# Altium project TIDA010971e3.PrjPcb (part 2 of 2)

## Sheet TIDA010971_AutoLabeling.SchDoc
size 431 x 279 mm; Date: Not shown in title block; ApprovedBy: Not shown in title block; CheckedBy: Not shown in title block; Author: Not shown in title block; CompanyName: Not shown in title block; Engineer: Not shown in title block; Organization: Not shown in title block; Address1: Not shown in title block; Address2: Not shown in title block; Address3: Not shown in title block; Address4: Not shown in title block; DocumentNumber: 2; Revision: Use project parameter SCH_Rev; SheetNumber: 6; SheetTotal: 6; PageSetup: Record=PageOptions¦CenterHorizontal=True¦CenterVertical=True¦PrintScale=1.00¦XCorrection=1.00¦YCorrection=1.00¦PrintKind=0¦BorderSize=5000000¦LeftOffset=0¦BottomOffset=0¦Orientation=2¦PaperLength=1000¦PaperWidth=1000¦Scale=100¦PaperSource=15¦PrintQuality=600¦MediaType=1¦DitherType=10¦PaperKind=Letter¦PrintScaleMode=1
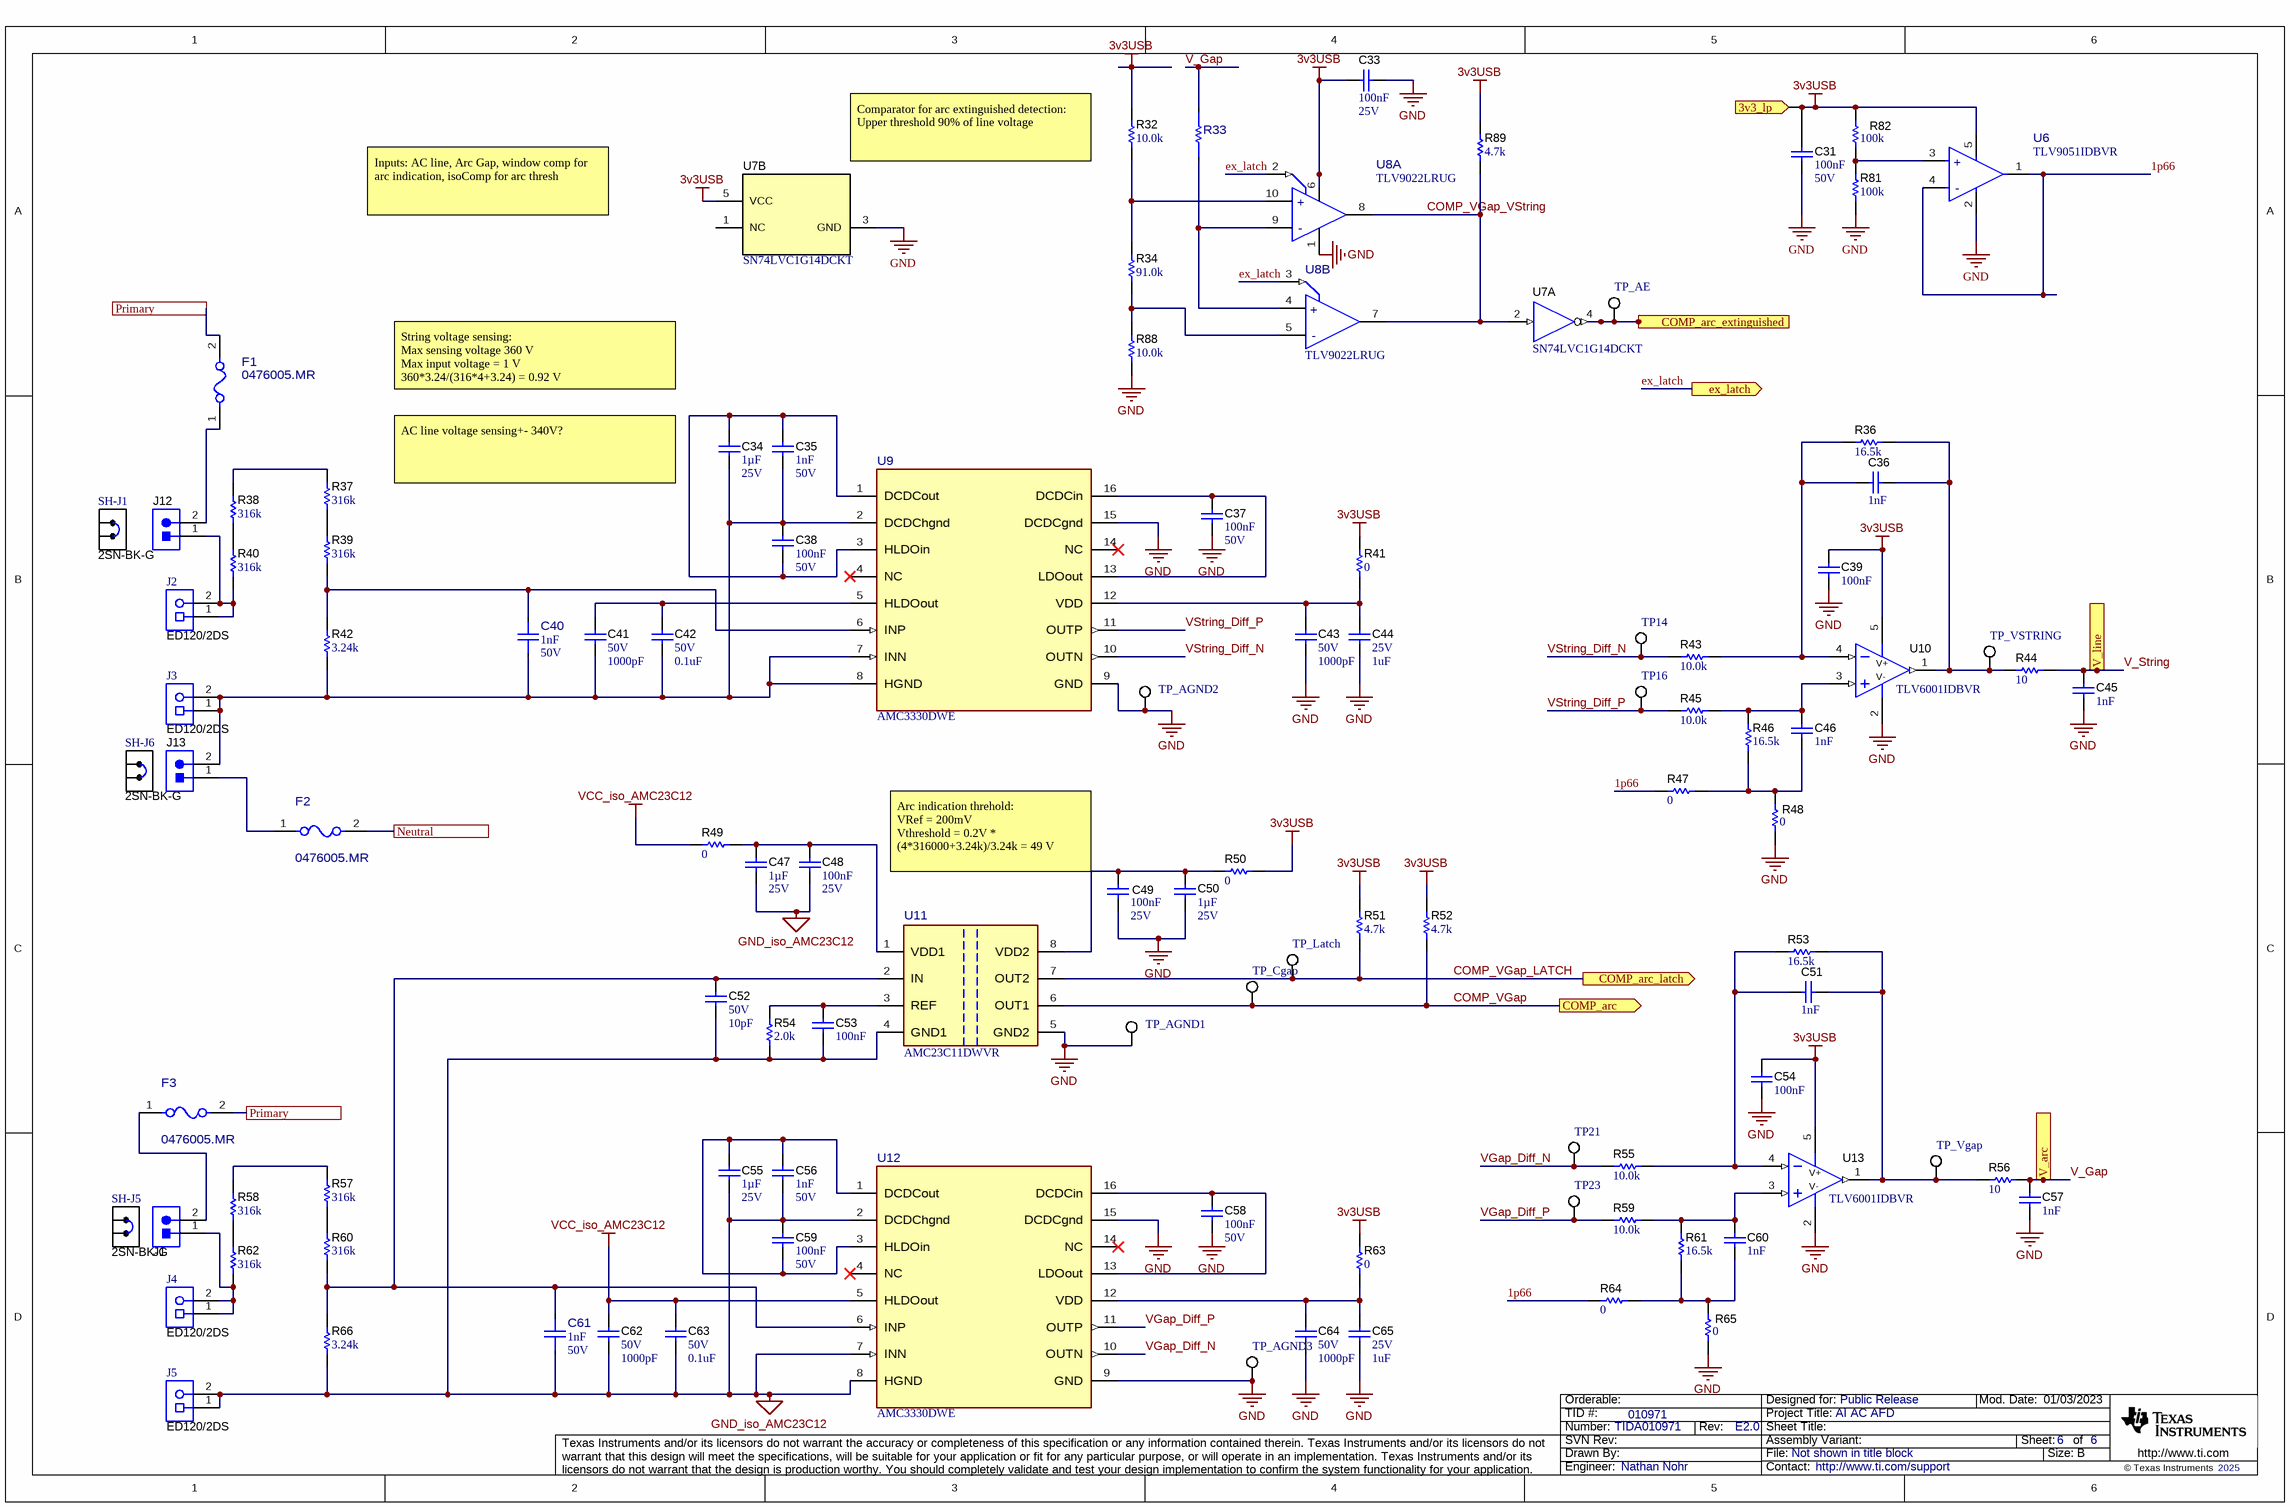
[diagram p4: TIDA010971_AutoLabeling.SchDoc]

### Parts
C31  Cap_F: 100nF  VDC_V: 50V  [0603S]  (hidden comment: C0603C104K5RACAUTO)
C33  Cap_F: 100nF  VDC_V: 25V  [0603S]  (hidden comment: C0603C104J3RACTU)
C34  Cap_F: 1µF  VDC_V: 25V  [0603S]  (hidden comment: 06033C105KAT2A)
C35  Cap_F: 1nF  VDC_V: 50V  [0603S]  (hidden comment: C0603C102K5RACTU)
C36  Cap_F: 1nF  [0603S]  (hidden comment: CL10C102JB8NNNC)
C37  Cap_F: 100nF  VDC_V: 50V  [0603S]  (hidden comment: C0603C104K5RACAUTO)
C38  Cap_F: 100nF  VDC_V: 50V  [0603S]  (hidden comment: C0603C104K5RACAUTO)
C39  Cap_F: 100nF  [0603S]  (hidden comment: C0603C104J3RAC)
C40  Cap_F: 1nF  VDC_V: 50V  [FP-C0603X102K5RAC7867_0603-MFG]  (hidden comment: C0603X102K5RAC7867)
C41  VDC_V: 50V  ValueDisplayed: 1000pF  [1206]  (hidden comment: 12065C102KAT2A)
C42  VDC_V: 50V  ValueDisplayed: 0.1uF  [1206]  (hidden comment: C1206C104K5RACTU)
C43  VDC_V: 50V  ValueDisplayed: 1000pF  [1206]  (hidden comment: 12065C102KAT2A)
C44  VDC_V: 25V  ValueDisplayed: 1uF  [1206]  (hidden comment: 12063C105KAT2A)
C45  Cap_F: 1nF  [0603S]  (hidden comment: CL10C102JB8NNNC)
C46  Cap_F: 1nF  [0603S]  (hidden comment: CL10C102JB8NNNC)
C47  Cap_F: 1µF  VDC_V: 25V  [0603S]  (hidden comment: 06033C105KAT2A)
C48  Cap_F: 100nF  VDC_V: 25V  [0603S]  (hidden comment: 06033C104KAT2A)
C49  Cap_F: 100nF  VDC_V: 25V  [0603S]  (hidden comment: 06033C104KAT2A)
C50  Cap_F: 1µF  VDC_V: 25V  [0603S]  (hidden comment: 06033C105KAT2A)
C51  Cap_F: 1nF  [0603S]  (hidden comment: CL10C102JB8NNNC)
C52  VDC_V: 50V  ValueDisplayed: 10pF  [0603S]  (hidden comment: C0603C100J5GACTU)
C53  Cap_F: 100nF  [0603S]  (hidden comment: 06033C104KAT2A)
C54  Cap_F: 100nF  [0603S]  (hidden comment: C0603C104J3RAC)
C55  Cap_F: 1µF  VDC_V: 25V  [0603S]  (hidden comment: 06033C105KAT2A)
C56  Cap_F: 1nF  VDC_V: 50V  [0603S]  (hidden comment: C0603C102K5RACTU)
C57  Cap_F: 1nF  [0603S]  (hidden comment: CL10C102JB8NNNC)
C58  Cap_F: 100nF  VDC_V: 50V  [0603S]  (hidden comment: C0603C104K5RACAUTO)
C59  Cap_F: 100nF  VDC_V: 50V  [0603S]  (hidden comment: C0603C104K5RACAUTO)
C60  Cap_F: 1nF  [0603S]  (hidden comment: CL10C102JB8NNNC)
C61  Cap_F: 1nF  VDC_V: 50V  [FP-C0603X102K5RAC7867_0603-MFG]  (hidden comment: C0603X102K5RAC7867)
C62  VDC_V: 50V  ValueDisplayed: 1000pF  [1206]  (hidden comment: 12065C102KAT2A)
C63  VDC_V: 50V  ValueDisplayed: 0.1uF  [1206]  (hidden comment: C1206C104K5RACTU)
C64  VDC_V: 50V  ValueDisplayed: 1000pF  [1206]  (hidden comment: 12065C102KAT2A)
C65  VDC_V: 25V  ValueDisplayed: 1uF  [1206]  (hidden comment: 12063C105KAT2A)
F1  0476005.MR  [FP-0476005.MR_SMT_FUSE_6MM1_2MM69-MFG]
F2  0476005.MR  [FP-0476005.MR_SMT_FUSE_6MM1_2MM69-MFG]
F3  0476005.MR  [FP-0476005.MR_SMT_FUSE_6MM1_2MM69-MFG]
J1  TSW-102-07-G-S  [TSW-102-07-G-S]  (value not drawn)
J2  ED120/2DS  [On-Shore_ED120_2DS]
J3  ED120/2DS  [On-Shore_ED120_2DS]
J4  ED120/2DS  [On-Shore_ED120_2DS]
J5  ED120/2DS  [On-Shore_ED120_2DS]
J12  TSW-102-07-G-S  [TSW-102-07-G-S]  (value not drawn)
J13  TSW-102-07-G-S  [TSW-102-07-G-S]  (value not drawn)
R32  ValueDisplayed: 10.0k  [0603]  (hidden comment: M55342K12B10E0T)
R33  CR0603-10W-000T  [FP-CR0603-10W-000T_0603-MFG]  (value not drawn)
R34  ValueDisplayed: 91.0k  [0603]  (hidden comment: RC0603FR-0791KL)
R36  ValueDisplayed: 16.5k  [0603S]  (hidden comment: RT0603BRD0716K5L)
R37  ValueDisplayed: 316k  [0805_HV1]  (hidden comment: CRCW0805316KFKEA)
R38  ValueDisplayed: 316k  [0805_HV1]  (hidden comment: CRCW0805316KFKEA)
R39  ValueDisplayed: 316k  [0805_HV1]  (hidden comment: CRCW0805316KFKEA)
R40  ValueDisplayed: 316k  [0805_HV1]  (hidden comment: CRCW0805316KFKEA)
R41  ValueDisplayed: 0  [0603S]  (hidden comment: RC0603JR-070RL)
R42  ValueDisplayed: 3.24k  [0603]  (hidden comment: RC0603FR-073K24L)
R43  ValueDisplayed: 10.0k  [0603S]  (hidden comment: RT0603BRD0710KL)
R44  ValueDisplayed: 10  [0603S]  (hidden comment: CRCW060310R0JNEA)
R45  ValueDisplayed: 10.0k  [0603S]  (hidden comment: RT0603BRD0710KL)
R46  ValueDisplayed: 16.5k  [0603S]  (hidden comment: RT0603BRD0716K5L)
R47  ValueDisplayed: 0  [0603S]  (hidden comment: RMCF0603ZT0R00)
R48  ValueDisplayed: 0  [0603S]  (hidden comment: RMCF0603ZT0R00)
R49  ValueDisplayed: 0  [0603S]  (hidden comment: RC0603JR-070RL)
R50  ValueDisplayed: 0  [0603S]  (hidden comment: RC0603JR-070RL)
R51  ValueDisplayed: 4.7k  [0603S]  (hidden comment: RC0603JR-074K7L)
R52  ValueDisplayed: 4.7k  [0603S]  (hidden comment: RC0603JR-074K7L)
R53  ValueDisplayed: 16.5k  [0603S]  (hidden comment: RT0603BRD0716K5L)
R54  ValueDisplayed: 2.0k  [0603]  (hidden comment: RC0603JR-072KL)
R55  ValueDisplayed: 10.0k  [0603S]  (hidden comment: RT0603BRD0710KL)
R56  ValueDisplayed: 10  [0603S]  (hidden comment: CRCW060310R0JNEA)
R57  ValueDisplayed: 316k  [0805_HV1]  (hidden comment: CRCW0805316KFKEA)
R58  ValueDisplayed: 316k  [0805_HV1]  (hidden comment: CRCW0805316KFKEA)
R59  ValueDisplayed: 10.0k  [0603S]  (hidden comment: RT0603BRD0710KL)
R60  ValueDisplayed: 316k  [0805_HV1]  (hidden comment: CRCW0805316KFKEA)
R61  ValueDisplayed: 16.5k  [0603S]  (hidden comment: RT0603BRD0716K5L)
R62  ValueDisplayed: 316k  [0805_HV1]  (hidden comment: CRCW0805316KFKEA)
R63  ValueDisplayed: 0  [0603S]  (hidden comment: RC0603JR-070RL)
R64  ValueDisplayed: 0  [0603S]  (hidden comment: RMCF0603ZT0R00)
R65  ValueDisplayed: 0  [0603S]  (hidden comment: RMCF0603ZT0R00)
R66  ValueDisplayed: 3.24k  [0603]  (hidden comment: RC0603FR-073K24L)
R81  ValueDisplayed: 100k  [0603]  (hidden comment: CRCW0603100KJNEAC)
R82  ValueDisplayed: 100k  [0603]  (hidden comment: CRCW0603100KJNEAC)
R88  ValueDisplayed: 10.0k  [0603]  (hidden comment: M55342K12B10E0T)
R89  ValueDisplayed: 4.7k  [0603S]  (hidden comment: RC0603JR-074K7L)
SH-J1  2SN-BK-G  [2SN-BK-G]
SH-J5  2SN-BK-G  [2SN-BK-G]
SH-J6  2SN-BK-G  [2SN-BK-G]
TP14  5007  [Keystone5007]  (value not drawn)
TP16  5007  [Keystone5007]  (value not drawn)
TP21  5007  [Keystone5007]  (value not drawn)
TP23  5007  [Keystone5007]  (value not drawn)
TP_AE  5007  [Keystone5007]  (value not drawn)
TP_AGND1  5007  [Keystone5007]  (value not drawn)
TP_AGND2  5007  [Keystone5007]  (value not drawn)
TP_AGND3  5007  [Keystone5007]  (value not drawn)
TP_Cgap  5007  [Keystone5007]  (value not drawn)
TP_Latch  5007  [Keystone5007]  (value not drawn)
TP_Vgap  5007  [Keystone5007]  (value not drawn)
TP_VSTRING  5007  [Keystone5007]  (value not drawn)
U6  TLV9051IDBVR  [DBV0005A-MFG]
U7  SN74LVC1G14DCKT  [DCK0005A_N]  (parts A,B of 2)
U8  TLV9022LRUG  [RUG0010A-MFG]  (parts A,B of 2)
U9  AMC3330DWE  [DWE0016A-MFG]
U10  TLV6001IDBVR  [DBV0005A_N]
U11  AMC23C11DWVR  [DWV0008A-MFG]
U12  AMC3330DWE  [DWE0016A-MFG]
U13  TLV6001IDBVR  [DBV0005A_N]

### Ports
3v3_lp (in), COMP_arc (out), COMP_arc_extinguished (out), COMP_arc_latch (out), ex_latch (out), Neutral, Primary, V_arc (out), V_line (out)

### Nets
3v3USB: C31.1 C33.2 C39.1 C54.1 R32.2 R41.2 R50.2 R51.2 R52.2 R63.2 R82.2 R89.2 U6.5(V+) U7.5(VCC) U8.6(V+) U10.5(V+) U13.5(V+) ; port 3v3_lp
GND: C31.2 C33.1 C37.2 C39.2 C43.2 C44.2 C45.2 C49.2 C50.2 C54.2 C57.2 C58.2 C64.2 C65.2 F2.2 R48.2 R65.2 R81.1 R88.1 TP_AGND1.1 TP_AGND2.1 TP_AGND3.1 U6.2(V-) U7.3(GND) U8.1(V-) U9.9(GND) U9.15(DCDCgnd) U10.2(V-) U11.5(GND2) U12.9(GND) U12.15(DCDCgnd) U13.2(V-) ; port Neutral  [project net AGND]
GND_iso_AMC23C12: C47.2 C48.2 C52.2 C53.2 C55.2 C56.2 C59.1 C61.1 C62.2 C63.2 J5.1 J5.2 R54.1 R66.1 U11.4(GND1) U12.2(DCDChgnd) U12.7(INN) U12.8(HGND)
VCC_iso_AMC23C12: C62.1 C63.1 R49.1 U12.5(HLDOout)
1p66: R47.1 R64.1 U6.1(OUT) U6.4(IN-)
COMP_arc_extinguished: TP_AE.1 U7.4(Y) ; port COMP_arc_extinguished
COMP_VGap: R52.1 TP_Cgap.1 U11.6(OUT1) ; port COMP_arc
COMP_VGap_LATCH: R51.1 TP_Latch.1 U11.7(OUT2) ; port COMP_arc_latch
COMP_VGap_VString: R89.1 U7.2(A) U8.7(OUT_B) U8.8(OUT_A)
ex_latch: U8.2(CLR_A) U8.3(CLR_B) ; port ex_latch
Primary: F1.2 F3.2 ; port Primary
V_Gap: C57.1 R33.2 R56.2 ; port V_arc
V_String: C45.1 R44.2 ; port V_line
VGap_Diff_N: R55.1 TP21.1 U12.10(OUTN)
VGap_Diff_P: R59.1 TP23.1 U12.11(OUTP)
VString_Diff_N: R43.1 TP14.1 U9.10(OUTN)
VString_Diff_P: R45.1 TP16.1 U9.11(OUTP)
NetC34_1: C34.1 C35.1 C38.2 U9.1(DCDCout) U9.3(HLDOin)
NetC34_2: C34.2 C35.2 C38.1 C40.1 C41.2 C42.2 J3.1 J3.2 J13.2 R42.1 U9.2(DCDChgnd) U9.7(INN) U9.8(HGND)
NetC36_1: C36.1 R36.2 R44.1 TP_VSTRING.1 U10.1(OUT)
NetC36_2: C36.2 R36.1 R43.2 U10.4(IN-)
NetC37_1: C37.1 U9.13(LDOout) U9.16(DCDCin)
NetC40_2: C40.2 R39.2 R42.2 U9.6(INP)
NetC41_1: C41.1 C42.1 U9.5(HLDOout)
NetC43_1: C43.1 C44.1 R41.1 U9.12(VDD)
NetC46_1: C46.1 R45.2 R46.2 U10.3(IN+)
NetC46_2: C46.2 R46.1 R47.2 R48.1
NetC47_1: C47.1 C48.1 R49.2 U11.1(VDD1)
NetC49_1: C49.1 C50.1 R50.1 U11.8(VDD2)
NetC51_1: C51.1 R53.2 R56.1 TP_Vgap.1 U13.1(OUT)
NetC51_2: C51.2 R53.1 R55.2 U13.4(IN-)
NetC52_1: C52.1 C61.2 R60.2 R66.2 U11.2(IN) U12.6(INP)
NetC53_1: C53.1 R54.2 U11.3(REF)
NetC55_1: C55.1 C56.1 C59.2 U12.1(DCDCout) U12.3(HLDOin)
NetC58_1: C58.1 U12.13(LDOout) U12.16(DCDCin)
NetC60_1: C60.1 R59.2 R61.2 U13.3(IN+)
NetC60_2: C60.2 R61.1 R64.2 R65.1
NetC64_1: C64.1 C65.1 R63.1 U12.12(VDD)
NetF1_1: F1.1 J12.2
NetF2_1: F2.1 J13.1
NetF3_1: F3.1 J1.2
NetJ1_1: J1.1 J4.1 J4.2 R62.2
NetJ2_1: J2.1 J2.2 J12.1 R40.2
NetR32_1: R32.1 R34.2 U8.10(IN+_A)
NetR33_1: R33.1 U8.4(IN+_B) U8.9(IN-_A)
NetR34_1: R34.1 R88.2 U8.5(IN-_B)
NetR37_1: R37.1 R38.2
NetR37_2: R37.2 R39.1
NetR38_1: R38.1 R40.1
NetR57_1: R57.1 R58.2
NetR57_2: R57.2 R60.1
NetR58_1: R58.1 R62.1
NetR81_2: R81.2 R82.1 U6.3(IN+)

Not connected (* = marked no-connect by the designer): U7 1(NC); U9 4(NC)* 14(NC)*; U12 4(NC)* 14(NC)*

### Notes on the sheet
- Comparator for arc extinguished detection:
  Upper threshold 90% of line voltage
- Inputs: AC line, Arc Gap, window comp for arc indication, isoComp for arc thresh
- String voltage sensing:
  Max sensing voltage 360 V
  Max input voltage = 1 V
  360*3.24/(316*4+3.24) = 0.92 V
- AC line voltage sensing+- 340V?
- (near C49) Arc indication threhold:
  VRef = 200mV
  Vthreshold = 0.2V * (4*316000+3.24k)/3.24k = 49 V

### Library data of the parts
C31 C37 C38 C58 C59 = CMP-0079602-1: CAP, CERM, 0.1 µF, 50 V,+/- 10%, X7R, AEC-Q200 Grade 1, 0603; Manufacturer: Kemet; TaMin_C: -55°C; Polarized: N; SizeAreaWB_mm2: 4.68; U/M: EA; Value: 0.1uF; TaMax_C: 125°C; SizeZ_mm: 1; SizeX_mm: 1.6; SizeY_mm: 0.8; Cap_Case: 0603; SizeArea_mm2: 1.28; AEC Qualified: Y; AEC Category: Q200; ValueDisplayed: 0.1µF
C33 = CMP-0006856-6: CAP, CERM, 0.1 uF, 25 V, +/- 5%, X7R, 0603; Manufacturer: Kemet; TaMin_C: -55°C; Polarized: N; SizeAreaWB_mm2: 4.68; Value1: Unknown; U/M: EA; Value: 0.1uF; TaMax_C: 125°C; SizeZ_mm: 1; SizeX_mm: 1.6; SizeY_mm: 0.8; Cap_Case: 0603; SizeArea_mm2: 1.28; AEC Category: Q200
C34 C47 C50 C55 = CMP-0006754-4: CAP, CERM, 1 uF, 25 V, +/- 10%, X7R, 0603; Manufacturer: AVX; TaMin_C: -55°C; Polarized: N; SizeAreaWB_mm2: 4.68; Value1: Unknown; U/M: EA; Value: 1uF; TaMax_C: 125°C; SizeZ_mm: 1; SizeX_mm: 1.6; SizeY_mm: 0.8; Cap_Case: 0603; SizeArea_mm2: 1.28; AEC Category: Q200
C35 C56 = CMP-0006847-4: CAP, CERM, 1000 pF, 50 V, +/- 10%, X7R, 0603; Manufacturer: Kemet; TaMin_C: -55°C; Polarized: N; SizeAreaWB_mm2: 4.68; Value1: Unknown; U/M: EA; Value: 1000pF; TaMax_C: 125°C; SizeZ_mm: 1; SizeX_mm: 1.6; SizeY_mm: 0.8; Cap_Case: 0603; SizeArea_mm2: 1.28; AEC Category: Q200
C36 C45 C46 C51 C57 C60 = CMP-0007114-5: CAP, CERM, 1000 pF, 50 V, +/- 5%, X7R, 0603; Manufacturer: Samsung Electro-Mechanics; TaMin_C: -55°C; Polarized: N; SizeAreaWB_mm2: 4.68; Value1: Unknown; U/M: EA; Value: 1000pF; TaMax_C: 125°C; SizeZ_mm: 1; SizeX_mm: 1.6; SizeY_mm: 0.8; Cap_Case: 0603; Value2: 50V; SizeArea_mm2: 1.28; AEC Category: Q200
C39 C54 = CMP-0006855-4: CAP, CERM, 0.1 uF, 25 V, +/- 5%, X7R, 0603; Manufacturer: Kemet; TaMin_C: -55°C; Polarized: N; SizeAreaWB_mm2: 4.68; Value1: Unknown; U/M: EA; Value: 0.1uF; TaMax_C: 125°C; SizeZ_mm: 1; SizeX_mm: 1.6; SizeY_mm: 0.8; Cap_Case: 0603; Value2: 25V; SizeArea_mm2: 1.28; AEC Category: Q200
C40 C61 = CMP-0045719-1: 1000 pF ±10% 50V Ceramic Capacitor X7R 0603 (1608 Metric); Manufacturer: KEMET; AEC Qualified: No; SizeZ_mm: 0.95mm; TempCo: 15%; ValueDisplayed: 1000pF; Value: 1nF
C41 C62 = CMP-0008530-2: CAP, CERM, 1000 pF, 50 V, +/- 10%, X7R, 1206; Manufacturer: AVX; TaMin_C: -55°C; ESR_ohm: 4.27d; Polarized: N; SizeAreaWB_mm2: 10.92; Value1: 0.427 ohm; U/M: EA; Value: 1000pF; TaMax_C: 125°C; SizeZ_mm: 1.35; SizeY_mm: 1.6; SizeArea_mm2: 5.12; Cap_F: 1nF; SizeX_mm: 3.2; AEC Category: Q200
C42 C63 = CMP-0008586-2: CAP, CERM, 0.1 uF, 50 V, +/- 10%, X7R, 1206; Manufacturer: Kemet; TaMin_C: -55°C; ESR_ohm: 59m; Polarized: N; SizeAreaWB_mm2: 10.92; Value1: 0.059 ohm; U/M: EA; Value: 0.1uF; TaMax_C: 125°C; SizeZ_mm: 1.35; SizeX_mm: 3.2; SizeY_mm: 1.6; SizeArea_mm2: 5.12; Cap_F: 100nF; IRMS_A: 1.2A; AEC Category: Q200
C43 C64 = CMP-0008530-2: CAP, CERM, 1000 pF, 50 V, +/- 10%, X7R, 1206; Manufacturer: AVX; TaMin_C: -55°C; ESR_ohm: 0.427; Polarized: N; SizeAreaWB_mm2: 10.92; Value1: 0.427 ohm; U/M: EA; Value: 1000pF; TaMax_C: 125°C; SizeZ_mm: 1.35; SizeX_mm: 3.2; SizeY_mm: 1.6; SizeArea_mm2: 5.12; Cap_F: 1nF; AEC Category: Q200
C44 C65 = CMP-0008509-2: CAP, CERM, 1 uF, 25 V, +/- 10%, X7R, 1206; Manufacturer: AVX; TaMin_C: -55°C; ESR_ohm: 13m; Polarized: N; SizeAreaWB_mm2: 10.92; Value1: 0.013 ohm; U/M: EA; Value: 1uF; TaMax_C: 125°C; SizeZ_mm: 1.35; SizeX_mm: 3.2; SizeY_mm: 1.6; SizeArea_mm2: 5.12; Cap_F: 1µF; AEC Category: Q200
C48 C49 = CMP-0006753-4: CAP, CERM, 0.1 uF, 25 V, +/- 10%, X7R, 0603; Manufacturer: AVX; TaMin_C: -55°C; ESR_ohm: 50m; Polarized: N; SizeAreaWB_mm2: 4.68; Value1: 0.05 ohm; U/M: EA; Value: 0.1uF; TaMax_C: 125°C; SizeZ_mm: 1; SizeX_mm: 1.6; SizeY_mm: 0.8; Cap_Case: 0603; SizeArea_mm2: 1.28; AEC Category: Q200
C52 = CMP-0006839-4: CAP, CERM, 10 pF, 50 V, +/- 5%, C0G/NP0, 0603; Manufacturer: Kemet; TaMin_C: -55°C; Polarized: N; SizeAreaWB_mm2: 4.68; Value1: Unknown; U/M: EA; Value: 10pF; TaMax_C: 125°C; SizeZ_mm: 1; SizeX_mm: 1.6; SizeY_mm: 0.8; Cap_Case: 0603; SizeArea_mm2: 1.28; AEC Category: Q200
C53 = CMP-0006753-4: CAP, CERM, 0.1 uF, 25 V, +/- 10%, X7R, 0603; Manufacturer: AVX; TaMin_C: -55°C; ESR_ohm: 50m; Polarized: N; SizeAreaWB_mm2: 4.68; Value1: 0.05 ohm; U/M: EA; Value: 0.1uF; TaMax_C: 125°C; SizeZ_mm: 1; SizeX_mm: 1.6; SizeY_mm: 0.8; Cap_Case: 0603; Value2: 25V; SizeArea_mm2: 1.28; AEC Category: Q200
F1-F3 = CMP-0121481-1: 5 A 250 V AC 125 V DC Fuse Board Mount (Cartridge Style Excluded) Surface Mount 2-SMD, Square End Block; Manufacturer: Littelfuse; Interrupt_AC: 100A; Interrupt_DC: 300A; MeltingTyp: 4A2Sec; SizeZ_mm: 2.94mm; VAC_V: 250V; Fuse Speed: Fast; AEC Qualified: No; Fuse Current: 5A; Res_ohm: 0.0157Ω
J1 J12 J13 = CMP-0075405-2: Header, 100mil, 2x1, Gold, TH; Manufacturer: Samtec; Pitch_mm: 2.54; Cert_VDE: N; Gender: Male; Cert_CSA: Y; Voltage_V: 550V; Green_REACh: Passed; Current_A: 6.3A; Green_Lifecycle: Active; Row_Count: 1
J2-J5 = CMP-0074910-1: Terminal Block, 5.08 mm, 2x1, Brass, TH; Manufacturer: On-Shore Technology; Cert_VDE: Y; CNHeader: False; Current_A: 15A; Green_Lifecycle: Not Set; Shrouded: N; Gender: Female; Green_REACh: Incomplete; Voltage_V: 300V; Row_Count: 1; Pitch_mm: 5.08; CT: True
R32 R88 = CMP-0080488-1: RES, 10.0 k, 1%, 0.1 W, 0603; Manufacturer: TT Electronics/IRC; Power_W: 100mW; TempCo: 100 ppm/C; SizeAreaWB_mm2: 4.68; Value_Code: 10k0; Value: 10.0k; EIA_Code: E96; Res_ohm: 10k; SizeX_mm: 1.6; SizeY_mm: 0.8; SizeZ_mm: 1; Value2: 0.1W; SizeArea_mm2: 1.28; AEC Qualified: N; AEC Category: Q200
R33 = CMP-0094956-1: 0 Ohms Jumper 0.1W, 1/10W Chip Resistor 0603 (1608 Metric) - Thick Film; Manufacturer: Venkel; Value: 0uΩ; Res_ohm: 0; Power_W: 100mW; SizeZ_mm: 0.55mm; AEC Qualified: No
R34 = CMP-0023318-5: RES, 91.0 k, 1%, 0.1 W, 0603; Manufacturer: Yageo; Power_W: 100mW; TempCo: 100 ppm/C; Value_Code: 91k0; Value: 91.0k; Res_ohm: 91k; SizeX_mm: 1.6; SizeY_mm: 0.8; SizeZ_mm: 1; Value2: 0.1W; SizeArea_mm2: 1.28; AEC Qualified: N; VDC_V: 75V; AEC Category: Q200; SizeAreaWB_mm2: 4.68
R36 R46 R53 R61 = CMP-0023800-3: RES, 16.5 k, 0.1%, 0.1 W, 0603; Manufacturer: Yageo America; Power_W: 100mW; TempCo: 25 ppm/C; Value_Code: 16k5; U/M: EA; Value: 16.5k; EIA_Code: E192; SizeX_mm: 1.6; SizeY_mm: 0.8; SizeZ_mm: 1; Value2: 0.1W; SizeArea_mm2: 1.28; VDC_V: 75V; AEC Category: Q200
R37-R40 R57 R58 R60 R62 = CMP-0021166-3: RES, 316 k, 1%, 0.125 W, AEC-Q200 Grade 0, 0805; Manufacturer: Vishay-Dale; Power_W: 125mW; TempCo: 100 ppm/C; Value: 316k; EIA_Code: E96; SizeX_mm: 2; SizeY_mm: 1.25; SizeZ_mm: 1.45; Value2: 0.125W; SizeArea_mm2: 2.5; AEC Qualified: Y; VDC_V: 150V; AEC Category: Q200; AEC Grade: 0
R41 R49 R50 R63 = CMP-0025885-5: RES, 0, 5%, 0.1 W, 0603; Manufacturer: Yageo; Power_W: 100mW; TempCo: 200 ppm/C; Value_Code: 0000; Value: 0; EIA_Code: E24; SizeX_mm: 1.6; SizeZ_mm: 1; Value2: 0.1W; SizeArea_mm2: 1.28; AEC Qualified: N; VDC_V: 75V; AEC Category: Q200; SizeY_mm: 0.8; SizeAreaWB_mm2: 4.68
R42 R66 = CMP-0023079-5: RES, 3.24 k, 1%, 0.1 W, 0603; Manufacturer: Yageo; Power_W: 100mW; TempCo: 100 ppm/C; Value_Code: 3k24; Value: 3.24k; EIA_Code: E96; SizeX_mm: 1.6; SizeY_mm: 0.8; SizeZ_mm: 1; Value2: 0.1W; SizeArea_mm2: 1.28; VDC_V: 75V; AEC Category: Q200; AEC Qualified: N; SizeAreaWB_mm2: 4.68
R43 R45 R55 R59 = CMP-0023653-3: RES, 10.0 k, 0.1%, 0.1 W, 0603; Manufacturer: Yageo America; Power_W: 100mW; TempCo: 25 ppm/C; Value_Code: 10k0; U/M: EA; Value: 10.0k; EIA_Code: E192; Res_ohm: 10k; SizeX_mm: 1.6; SizeY_mm: 0.8; SizeZ_mm: 1; Value2: 0.1W; SizeArea_mm2: 1.28; VDC_V: 75V; AEC Category: Q200
R44 R56 = CMP-0025703-4: RES, 10, 5%, 0.1 W, AEC-Q200 Grade 0, 0603; Manufacturer: Vishay-Dale; Power_W: 100mW; TempCo: 200 ppm/C; Value_Code: 10R0; Value: 10; EIA_Code: E24; SizeX_mm: 1.6; SizeY_mm: 0.8; SizeZ_mm: 1; Value2: 0.1W; SizeArea_mm2: 1.28; AEC Qualified: Y; VDC_V: 75V; AEC Category: Q200; AEC Grade: 0
R47 R48 R64 R65 = CMP-0023343-3: RES, 0, 1%, 0.1 W, AEC-Q200 Grade 0, 0603; Manufacturer: Stackpole Electronics Inc; Power_W: 100mW; TempCo: ppm/C; U/M: EA; Value: 0; SizeX_mm: 1.6; SizeY_mm: 0.8; SizeZ_mm: 1; Value2: 0.1W; SizeArea_mm2: 1.28; AEC Qualified: Y; AEC Category: Q200
R51 R52 R89 = CMP-0025927-5: RES, 4.7 k, 5%, 0.1 W, 0603; Manufacturer: Yageo; Power_W: 100mW; TempCo: 100 ppm/C; Value_Code: 4k70; Value: 4.7k; EIA_Code: E24; SizeX_mm: 1.6; SizeY_mm: 0.8; SizeZ_mm: 1; Value2: 0.1W; SizeArea_mm2: 1.28; AEC Qualified: N; VDC_V: 75V; AEC Category: Q200; SizeAreaWB_mm2: 4.68
R54 = CMP-0025909-5: RES, 2.0 k, 5%, 0.1 W, 0603; Manufacturer: Yageo; Power_W: 100mW; TempCo: 100 ppm/C; Value_Code: 2k00; Value: 2.0k; EIA_Code: E24; Res_ohm: 2k; SizeX_mm: 1.6; SizeY_mm: 0.8; SizeZ_mm: 1; Value2: 0.1W; SizeArea_mm2: 1.28; AEC Qualified: N; VDC_V: 75V; AEC Category: Q200; SizeAreaWB_mm2: 4.68
R81 R82 = CMP-0082530-1: RES, 100 k, 5%, 0.1 W, 0603; Manufacturer: Vishay-Dale; Power_W: 100mW; TempCo: 200 ppm/C; SizeAreaWB_mm2: 4.68; Value: 100k; EIA_Code: E24; SizeX_mm: 1.6; SizeY_mm: 0.8; SizeZ_mm: 1; Value2: 0.1W; SizeArea_mm2: 1.28; AEC Qualified: N; VDC_V: 75V; AEC Category: Q200
SH-J1 SH-J5 SH-J6 = CMP-0003641-1: Shunt, 2mm, Gold plated, Black; Manufacturer: Samtec; Note: You can "mate" this to a header by matching the designator.  i.e. use SH-J3 for header J3; Value: 1x2
TP14 TP16 TP21 TP23 TP_AE TP_AGND1-TP_AGND3 TP_Cgap TP_Latch TP_Vgap TP_VSTRING = CMP-0055144-2: Test Point, Compact, White, TH; Manufacturer: Keystone Electronics; CNHeader: FALSE; Green_Lifecycle: Active; Green_REACh: Passed; ContactFinish: Silver; CT: TRUE
U6 = CMP-0090312-1: General Purpose Amplifier 1 Circuit Rail-to-Rail SOT-23-5; Manufacturer: Texas Instruments; Output Current Per Channel: 50mA; Gain Bandwidth: 5MHz; Nominal Supply Current: 330uA; Min Supply Voltage: 1.8V; Standoff Height: 0mm; TJmax_C: +150°C; Input Offset Voltage: 0.33mV; Number Of Channels: 1; AEC Qualified: No; Max Supply Voltage: 5.5V; SizeZ_mm: 1.45mm; Input Bias Current: 0.000002uA; Voltage Gain: 104dB; TaMin_C: -40°C
U7 = CMP-0051644-4: Single Schmitt-Trigger Inverter, DCK0005A (SOT-SC70-5); Manufacturer: Texas Instruments; Alternate PartNumber: SN74LVC1G14DCKR; 3-State Output: No; Bits(#): 1; Input Type: CMOS/TTL; Schmitt Trigger: Yes; Rating: Catalog; VCC(Max)(V): 5.5; tpd @ Nom Voltage(Max)(ns): 11,6.5,5.5,5; Output Drive (IOL/IOH)(Max)(mA): 32/-32; F @ Nom Voltage(Max)(Mhz): 150; Logic: Inverting; Voltage(Nom)(V): 1.8,2.5,3.3,5; ICC @ Nom Voltage(Max)(mA): 0.01; Output Type: CMOS; VCC(Min)(V): 1.65; AEC Category: Q200; AEC Qualified: N; CompType: IC; Green_Lifecycle: Active; Green_REACh: Passed; SizeAreaWB_mm2: 9.3; SizeArea_mm2: 4.2; SizeX_mm: 2.1; SizeY_mm: 2.0; SizeZ_mm: 1.1
U8 = CMP-0122167-3: Precision, Self-Latching Comparator; Manufacturer: Texas Instruments; SizeZ_mm: 0.4mm; AEC Qualified: No; Input Bias Current: 0.000005uA; Input Offset Voltage: 0.3mV; Max Supply Voltage: 5.5V; Min Supply Voltage: 1.65V; Nominal Supply Current: 20uA; Number Of Channels: 2; Output Current Per Channel: 100mA; Standoff Height: 0mm; TaMax_C: +125°C; TaMin_C: -40°C; TJmax_C: +150°C; AEC Category: Q200; CompType: IC
U9 U12 = CMP-0088720-4: Precision, ±1-V Input, Reinforced Isolated Amplifier With Integrated DC/DC Converter; Manufacturer: Texas Instruments; TJmax_C: +150°C; SizeZ_mm: 2.65mm; AEC Category: Q200; Standoff Height: 0.1mm; AEC Qualified: No; TaMax_C: +125°C; TaMin_C: -40°C; CompType: IC; Max Supply Voltage: 5.5V; Nominal Supply Current: 27.5-28.5mA; Min Supply Voltage: 3V
U10 U13 = CMP-0073547-1: 1-MHz, Low-Power Operational Amplifier for Cost-Sensitive Systems, DBV0005A (SOT-23-5); Alternate PartNumber: TLV6001IDBVT; Alternate Manufacturer: Texas Instruments; SizeAreaWB_mm2: 14.82; U/M: EA; SizeZ_mm: 1.45; SizeX_mm: 2.8; SizeY_mm: 2.9; SizeArea_mm2: 8.12; CompType: IC
U11 = CMP-0092823-1: High-Speed Reinforced Comparator w/ Reference, Open-Drain and Push-Pull Output; Manufacturer: Texas Instruments; Number Of Channels: 1; Standoff Height: 0.36mm; SizeZ_mm: 2.8mm

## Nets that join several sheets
3v3: TIDA010971_AFE (6 pins), TIDA010971_Power (3v3.1 C27.1 D10.1 U5.5)
3v3USB: TIDA010971_Connectors_MCU_Labeling (J1/J3.1), TIDA010971_AutoLabeling (17 pins)
AGND: TIDA010971_AFE (45 pins), TIDA010971_Power (16 pins), TIDA010971_Connectors_MCU_Labeling (8 pins), TIDA010971_AutoLabeling (32 pins)
5v_led: TIDA010971_Power (8 pins), TIDA010971_Connectors_MCU_Labeling (D9.1 R80.1)
ADC_Log: TIDA010971_AFE (C9.1 R11.2 TP8.1), TIDA010971_Connectors_MCU_Labeling (J1/J3.6)
ADC_Voltage sense: TIDA010971_AFE (C17.1 R20.2 TP19.1), TIDA010971_Connectors_MCU_Labeling (J1/J3.25)
COMP_arc_extinguished: TIDA010971_Connectors_MCU_Labeling (J2/J4.35), TIDA010971_AutoLabeling (TP_AE.1 U7.4)
COMP_VGap: TIDA010971_Connectors_MCU_Labeling (J2/J4.36), TIDA010971_AutoLabeling (R52.1 TP_Cgap.1 U11.6)
COMP_VGap_LATCH: TIDA010971_Connectors_MCU_Labeling (J2/J4.34), TIDA010971_AutoLabeling (R51.1 TP_Latch.1 U11.7)
Current_BP: TIDA010971_AFE (C7.1 R22.2 TP12.1), TIDA010971_Connectors_MCU_Labeling (J1/J3.26)
Current_LP: TIDA010971_AFE (C19.1 R18.2 TP17.1), TIDA010971_Connectors_MCU_Labeling (J1/J3.27)
ex_latch: TIDA010971_Connectors_MCU_Labeling (J2/J4.37), TIDA010971_AutoLabeling (U8.2 U8.3)
FreqDetect: TIDA010971_AFE (R75.1), TIDA010971_Connectors_MCU_Labeling (J1/J3.8)
Primary: TIDA010971_AFE (R16.2), TIDA010971_Power (6 pins), TIDA010971_Connectors_MCU_Labeling (D8.1 K1.4 R71.1), TIDA010971_AutoLabeling (F1.2 F3.2)
V_Gap: TIDA010971_Connectors_MCU_Labeling (J1/J3.24), TIDA010971_AutoLabeling (C57.1 R33.2 R56.2)
V_String: TIDA010971_Connectors_MCU_Labeling (J1/J3.23), TIDA010971_AutoLabeling (C45.1 R44.2)

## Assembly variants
001: not fitted C24 C30 FID1 FID2 FID3 J7 R48 R65 R70 R71 R73 R81 R82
